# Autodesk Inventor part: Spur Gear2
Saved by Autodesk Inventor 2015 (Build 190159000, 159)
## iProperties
Created: 2014-06
Part Number: Spur Gear2
Material: Steel
Document SubType Name: Modeling
Designer: User
Categories: <?xml version="1.0" encoding="UTF-16"?> <MemberInstance><Categories><FamilyTemplate><FamilyTemplateParameter ValueType="xs:double" Id="1" ObjectReferenceKey="da
Density: 1 g/cm^3
Appearance: Steel
CustomPartVersion: 1
Author: User
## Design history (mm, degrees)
sketch "Sketch1"
  geometry: C1 r 10.888 at (0, 0)
  constraints: 1 centre point
  dimensions: "d0" = 21.77632 diameter of C1 (= da_da)
extrude "Extrusion1" new body sketch "Sketch1" distance "d1" = 2 (= da_b); taper "d2" = 0 deg
workplane "Work Plane2"
sketch "Sketch2"
  geometry: C1 r 10.888 at (0, 0) reference; C2 r 9.9 at (0, 0)
  constraints: 1 centre point, 1 coincident
  dimensions: "d3" = 19.8 diameter of C2 (= da_dw)
feature "Pitch Diameter" sketch "Sketch2" dims "d4" = 10, "d5" = 0
workplane "Work Plane8"
workplane "Work Plane9"
feature "Spur Gear" dims "da_b" = 2, "da_d" = 19.17791, "da_aw" = 19.8, "da_da" = 21.77632, "da_df" = 17.32368, "da_dw" = 19.8, angle "da_beta" = 55 deg, "da_lefttooth" = 0, "da_righttooth" = 10
body "Solid1"
body "Srf1"
other parameters: "d16" = 19.8 (= da_aw), "d17" = 0, "d34" = 2.85599 (computed from da_z), "d39" = 0, "d41" = 0, "d43" = 19.8 (= da_aw), "d46" = 19.8 (= da_aw), "d47" = 0, "d48" = 0
